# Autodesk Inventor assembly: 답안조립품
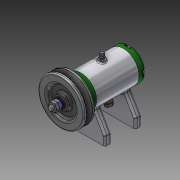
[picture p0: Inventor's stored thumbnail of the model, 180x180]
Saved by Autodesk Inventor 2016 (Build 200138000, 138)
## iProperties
Created: 2018-05
Part Number: 답안조립품
Document SubType Name: Assembly
Designer: Administrator
Author: Administrator
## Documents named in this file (16)
- C:\Users\Administrator\Desktop\480507V1026\답안조립품.iam
- C:\Users\Administrator\Desktop\480507V1026\본체.ipt
- C:\Users\Administrator\Desktop\480507V1026\축.ipt
- C:\Users\Administrator\Desktop\480507V1026\베어링 6002.ipt
- C:\Users\Administrator\Desktop\480507V1026\앞커버.ipt
- C:\Users\Administrator\Desktop\480507V1026\오일 실 15 25 7.ipt
- C:\Users\Administrator\Desktop\480507V1026\볼트 M4x12.ipt
- C:\Users\Administrator\Desktop\480507V1026\키 3x3x12.ipt
- C:\Users\Administrator\Desktop\480507V1026\V벨트풀리.ipt
- C:\Users\Administrator\Desktop\480507V1026\와셔 8x17.ipt
- C:\Users\Administrator\Desktop\480507V1026\스프링와셔 8.ipt
- C:\Users\Administrator\Desktop\480507V1026\너트 M8.ipt
- C:\Users\Administrator\Desktop\480507V1026\뒤커버.ipt
- C:\Users\Administrator\Desktop\480507V1026\니플 M6x0.75.ipt
- C:\Users\Administrator\Desktop\480507V1026\와셔 6x11.5.ipt
- C:\Users\Administrator\Desktop\480507V1026\볼트 M6x8.ipt
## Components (1 placed, 1 different names)
1. V벨트풀리:1
